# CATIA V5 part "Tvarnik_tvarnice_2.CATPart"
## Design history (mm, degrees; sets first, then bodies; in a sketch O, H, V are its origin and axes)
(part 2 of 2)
Body25 "Tvarnice"
  Sketch40 on face of Solid23, origin (1.6, 0, 0), H (0, 1, 0), V (0, 0, 1)
    line L1 (80, 80) -> (80, -80)
    line L2 (80, -80) -> (-80, -80)
    line L3 (-80, -80) -> (-80, 80)
    line L4 (-80, 80) -> (80, 80)
    length L4 = 160
    length L1 = 160
    vertical: L1 V, L3 V
    horizontal: L2 H, L4 H
    equidistance: L1 L3 O, L2 L4 O
  Pocket13: profile Sketch40, direction (-1, 0, 0), length 16
  Body26 "Vicko"
    Solid24: linked copy from another document
  Remove2: tool Body26
  Trim1: faces to keep start face of Pocket13, faces to remove start face of Pocket13 (x35)
  Sketch41 on start face of Pocket13, origin (1.6, 0, 0), H (0, 1, 0), V (0, 0, 1)
    projected circle E1 centre (26.45, -66.45) radius 5.1 from start face of Pocket13
    projected circle E2 centre (-26.2, -66.08) radius 5.1 from start face of Pocket13
    projected circle E3 centre (-68.2522, 13.0002) radius 5.1 from start face of Pocket13
    projected circle E4 centre (-35.5625, 59.6882) radius 5.1 from start face of Pocket13
    projected circle E5 centre (38.2049, 58.0324) radius 5.1 from start face of Pocket13
    projected circle E6 centre (70.2785, -7.2128) radius 5.1 from start face of Pocket13
  Pad6: profile Sketch41, direction (-1, 0, 0), length 3
  Sketch42 on end face of Pad6, origin (-1.4, 0, 0), H (0, 1, 0), V (0, 0, 1)
    projected circle E1 centre (70.2785, -7.2128) radius 3 from end face of Pad6
    projected circle E2 centre (38.2049, 58.0324) radius 3 from end face of Pad6
    projected circle E4 centre (-68.2522, 13.0002) radius 3 from edge [face of Solid24 | end face of Pad6]
    projected circle E5 centre (-26.2, -66.08) radius 3 from end face of Pad6
    projected circle E6 centre (26.45, -66.45) radius 3 from end face of Pad6
  Pad7: profile Sketch42, direction (-1, 0, 0), length 0.3
  Sketch43 on start face of Pocket13, origin (1.6, 0, 0), H (0, 1, 0), V (0, 0, 1)
    projected arc E1 centre (-39.7026, -63.67) radius 8 from (-33.5229, -68.7505) to (-31.75, -64.54) ccw from edge [face of Solid23 | face of Solid23]
    projected arc E3 centre (-38.7, -63.15) radius 7 from (-37.0577, -56.3454) to (-42.5892, -57.3299) ccw from edge [face of Solid23 | face of Solid23]
    projected arc E4 centre (-42.6448, -57.2467) radius 0.1 from (-42.6019, -57.337) to (-42.5892, -57.3299) ccw from edge [face of Solid23 | face of Solid23]
    projected line E5 (-42.9183, -57.4874) -> (-42.6019, -57.337) from edge [face of Solid23 | face of Solid23]
    projected arc E6 centre (-43.1328, -57.0357) radius 0.5 from (-43.5459, -57.3175) to (-42.9183, -57.4874) ccw from edge [face of Solid23 | face of Solid23]
    projected line E7 (-44.5334, -55.87) -> (-43.5459, -57.3175) from edge [face of Solid23 | face of Solid23]
    projected arc E8 centre (-44.9464, -56.1518) radius 0.5 from (-44.5334, -55.87) to (-44.634, -55.7614) ccw from edge [face of Solid23 | face of Solid23]
    projected arc E9 centre (0, 0) radius 71.425 from (-64.1739, -31.3568) to (-44.634, -55.7614) ccw from edge [face of Solid23 | face of Solid23]
    projected arc E10 centre (0, 0) radius 71.425 from (-71.1311, 6.4726) to (-64.1739, -31.3568) ccw from edge [face of Solid23 | face of Solid23]
    projected arc E11 centre (-73.1229, 6.6538) radius 2 from (-71.1311, 6.4726) to (-71.9052, 8.2404) ccw from edge [face of Solid23 | face of Solid23]
    projected arc E12 centre (-68.2522, 13.0002) radius 6 from (-69.8997, 18.7696) to (-71.9052, 8.2404) ccw from edge [face of Solid23 | face of Solid23]
    projected arc E13 centre (-70.4489, 20.6927) radius 2 from (-69.8997, 18.7696) to (-68.5299, 20.1291) ccw from edge [face of Solid23 | face of Solid23]
    projected arc E14 centre (0, 0) radius 71.425 from (-42.3563, 57.5107) to (-68.5299, 20.1291) ccw from edge [face of Solid23 | face of Solid23]
    projected arc E15 centre (-43.5423, 59.121) radius 2 from (-42.3563, 57.5107) to (-41.5474, 59.2628) ccw from edge [face of Solid23 | face of Solid23]
    projected arc E16 centre (-35.5625, 59.6882) radius 6 from (-32.3394, 64.749) to (-41.5474, 59.2628) ccw from edge [face of Solid23 | face of Solid23]
    projected arc E17 centre (-31.265, 66.4359) radius 2 from (-32.3394, 64.749) to (-30.8799, 64.4733) ccw from edge [face of Solid23 | face of Solid23]
    projected arc E18 centre (-31.265, 66.4359) radius 2 from (-30.8799, 64.4733) to (-30.4134, 64.6263) ccw from edge [face of Solid23 | face of Solid23]
    projected arc E19 centre (0, 0) radius 71.425 from (33.2826, 63.1965) to (-30.4134, 64.6263) ccw from edge [face of Solid23 | face of Solid23]
    projected arc E20 centre (34.2145, 64.9661) radius 2 from (33.2826, 63.1965) to (34.4133, 62.976) ccw from edge [face of Solid23 | face of Solid23]
    projected arc E21 centre (34.2145, 64.9661) radius 2 from (34.4133, 62.976) to (35.2121, 63.2327) ccw from edge [face of Solid23 | face of Solid23]
    projected arc E22 centre (38.2049, 58.0324) radius 6 from (44.1647, 57.3389) to (35.2121, 63.2327) ccw from edge [face of Solid23 | face of Solid23]
    projected arc E23 centre (46.1513, 57.1077) radius 2 from (44.1647, 57.3389) to (44.1679, 56.8506) ccw from edge [face of Solid23 | face of Solid23]
    projected arc E24 centre (46.1513, 57.1077) radius 2 from (44.1679, 56.8506) to (44.8942, 55.5522) ccw from edge [face of Solid23 | face of Solid23]
    projected arc E25 centre (0, 0) radius 71.425 from (68.6438, 19.7372) to (44.8942, 55.5522) ccw from edge [face of Solid23 | face of Solid23]
    projected arc E26 centre (68.5477, 19.7095) radius 0.1 from (68.6445, 19.7346) to (68.6438, 19.7372) ccw from edge [face of Solid23 | face of Solid23]
    projected arc E27 centre (68.5476, 19.7096) radius 0.1001 from (68.6357, 19.662) to (68.6445, 19.7346) ccw from edge [face of Solid23 | face of Solid23]
    projected arc E28 centre (68.5477, 19.7095) radius 0.1 from (68.6344, 19.6597) to (68.6357, 19.662) ccw from edge [face of Solid23 | face of Solid23]
    projected line E29 (65.7164, 14.5806) -> (68.6344, 19.6597) from edge [face of Solid23 | face of Solid23]
    projected arc E30 centre (69.5316, 12.3887) radius 4.4 from (65.7164, 14.5806) to (70.8571, 8.1931) ccw from edge [face of Solid23 | face of Solid23]
    projected arc E31 centre (70.8872, 8.0978) radius 0.1 from (70.9819, 8.13) to (70.8571, 8.1931) ccw from edge [face of Solid23 | face of Solid23]
    projected arc E33 centre (69.7785, -6.9628) radius 6 from (72.2645, -12.4235) to (75.4588, -5.0305) ccw from edge [face of Solid23 | face of Solid23]
    projected line E34 (70.9819, 8.13) -> (75.4588, -5.0305) from edge [face of Solid23 | face of Solid23]
    projected arc E35 centre (72.4717, -12.8786) radius 0.5 from (72.2645, -12.4235) to (72.1405, -12.504) ccw from edge [face of Solid23 | face of Solid23]
    projected line E36 (72.1405, -12.504) -> (72.0071, -12.6219) from edge [face of Solid23 | face of Solid23]
    projected line E37 (71.6567, -12.9317) -> (72.0071, -12.6219) from edge [face of Solid23 | face of Solid23]
    projected line E38 (70.1987, -14.2207) -> (71.6567, -12.9317) from edge [face of Solid23 | face of Solid23]
    projected arc E39 centre (70.861, -14.9699) radius 1 from (70.1987, -14.2207) to (69.8826, -14.7632) ccw from edge [face of Solid23 | face of Solid23]
    projected arc E40 centre (0, 0) radius 71.425 from (34.7, -62.4295) to (69.8826, -14.7632) ccw from edge [face of Solid23 | face of Solid23]
    projected line E41 (34.7, -63.3874) -> (34.7, -62.4295) from edge [face of Solid23 | face of Solid23]
    projected line E42 (34.7, -63.3874) -> (34.6998, -63.4087) from edge [face of Solid23 | face of Solid23]
    projected arc E43 centre (34.5768, -63.4037) radius 0.123 from (34.6907, -63.4503) to (34.6998, -63.4087) ccw from edge [face of Solid23 | face of Solid23]
    projected arc E45 centre (39.6, -65.7) radius 5.4 from (34.6823, -63.4692) to (34.2, -65.7) ccw from edge [face of Solid23 | face of Solid23]
    projected line E46 (34.6907, -63.4503) -> (34.6823, -63.4692) from edge [face of Solid23 | face of Solid23]
    projected arc E47 centre (27.2, -65.7) radius 7 from (29.0596, -72.4485) to (34.2, -65.7) ccw from edge [face of Solid23 | face of Solid23]
    projected line E48 (27.2179, -73.1928) -> (29.0487, -72.4522) from edge [face of Solid23 | face of Solid23]
    projected line E49 (27.2179, -73.1928) -> (27.1999, -73.1995) from edge [face of Solid23 | face of Solid23]
    projected line E50 (27.1999, -73.1995) -> (27.1807, -73.2) from edge [face of Solid23 | face of Solid23]
    projected line E51 (26.95, -73.2) -> (27.1807, -73.2) from edge [face of Solid23 | face of Solid23]
    projected arc E52 centre (26.95, -65.95) radius 7.25 from (19.7, -65.95) to (26.95, -73.2) ccw from edge [face of Solid23 | face of Solid23]
    projected line E53 (19.7, -54.5084) -> (19.7, -65.95) from edge [face of Solid23 | face of Solid23]
    projected arc E54 centre (10.55, -54.5084) radius 9.15 from (19.7, -54.5084) to (14.5407, -46.2746) ccw from edge [face of Solid23 | face of Solid23]
    projected arc E55 centre (10.55, -54.5084) radius 9.15 from (14.5407, -46.2746) to (12.2, -45.5084) ccw from edge [face of Solid23 | face of Solid23]
    projected arc E56 centre (-1.5593, -117.2) radius 73 from (12.028, -45.4756) to (8.5876, -44.9086) ccw from edge [face of Solid23 | face of Solid23]
    projected arc E57 centre (-1.5593, -117.2) radius 73 from (12.2, -45.5084) to (12.028, -45.4756) ccw from edge [face of Solid23 | face of Solid23]
    projected arc E58 centre (-1.5593, -117.2) radius 73 from (8.5876, -44.9086) to (-13.7, -45.2166) ccw from edge [face of Solid23 | face of Solid23]
    projected arc E59 centre (-12.6167, -52.2166) radius 7.0833 from (-13.7, -45.2166) to (-14.8563, -45.4967) ccw from edge [face of Solid23 | face of Solid23]
    projected arc E60 centre (-12.6167, -52.2166) radius 7.0833 from (-14.8563, -45.4967) to (-19.7, -52.2166) ccw from edge [face of Solid23 | face of Solid23]
    projected line E61 (-19.7, -52.2166) -> (-19.7, -67.2) from edge [face of Solid23 | face of Solid23]
    projected arc E62 centre (-25.7, -67.2) radius 6 from (-25.7, -73.2) to (-19.7, -67.2) ccw from edge [face of Solid23 | face of Solid23]
    projected line E63 (-25.7, -73.2) -> (-25.725, -73.1988) from edge [face of Solid23 | face of Solid23]
    projected line E64 (-25.7279, -73.1975) -> (-25.7474, -73.1876) from edge [face of Solid23 | face of Solid23]
    point P123 (-25.7279, -73.1975)
    projected line E65 (-25.7474, -73.1876) -> (-28.2581, -71.7985) from edge [face of Solid23 | face of Solid23]
    projected line E66 (-33.494, -68.9015) -> (-28.2581, -71.7985) from edge [face of Solid23 | face of Solid23]
    projected arc E67 centre (-33.4456, -68.814) radius 0.1 from (-33.5229, -68.7505) to (-33.494, -68.9015) ccw from edge [face of Solid23 | face of Solid23]
    line L1 (29.0487, -72.4522) -> (29.0596, -72.4485)
    line L2 (-25.7279, -73.1975) -> (-25.725, -73.1988)
    point P131 (-25.7279, -73.1975)
    coincidence: P131 E64, P123 P131
  Pad8: profile Sketch43, direction (-1, 0, 0), length 0.3
  Sketch44 on end face of Pocket13, origin (-14.4, 0, 0), H (0, -1, 0), V (0, 0, 1)
    line L1 (90, 90) -> (90, -90)
    line L2 (90, -90) -> (-90, -90)
    line L3 (-90, -90) -> (-90, 90)
    line L4 (-90, 90) -> (90, 90)
    length L4 = 180
    length L1 = 180
    vertical: L1 V, L3 V
    horizontal: L2 H, L4 H
    equidistance: L1 L3 O, L2 L4 O
  Pocket14: profile Sketch44, direction (-1, 0, 0), length 30
  DatumCurve25
  DatumCurve26
  Body27 "MANIFOLD_SOLID_BREP #135"
  Remove3: tool Body27
  DatumSurface19
  Sketch45 on zx-plane, origin (0, 0, 0), H (-1, 0, 0), V (0, 0, 1)
    point P1 (5.1, 0)
    line L1 (5.1, 0) -> (5.1, 1)
    arc A1 centre (8.8103, -0.4945) radius 4 from (5.1, 1) to (8.6, 3.5) cw
    line L2 (8.6, 3.5) -> (8.6, 0)
    point P5 (8.6, 0)
    line L3 (8.6, 0) -> (5.1, 0)
    length L1 = 1
    radius A1 = 4
    length L2 = 3.5
    length L3 = 3.5
    distance L1 V = 5.1
    coincidence: P1 H, P5 H
    vertical: L1 V, L2 V
    horizontal: L3 H
  Shaft1: profile Sketch45, axis Sketch45.L3, angle 360
  Sketch46 on end face of Pocket14, origin (-44.4, 0, 0), H (0, -1, 0), V (0, 0, 1)
    arc A1 centre (0, 0) radius 18.5 from (-18.5, 0) to (18.5, 0) ccw
    arc A2 centre (0, 0) radius 18.5 from (18.5, 0) to (-18.5, 0) ccw
  Pad9: profile Sketch46, direction (1, 0, 0), length 29
  DatumCurve27
  DatumCurve28
  Sketch47 on end face of Pad9, origin (-15.4, 0, 0), H (0, -1, 0), V (0, 0, 1)
    projected arc E1 centre (0, 0) radius 8.5 from (8.5, 0) to (-8.5, 0) ccw from edge of DatumCurve27
    projected arc E2 centre (0, 0) radius 8.5 from (-8.5, 0) to (8.5, 0) ccw from edge of DatumCurve28
  Pad10: profile Sketch47, direction (1, 0, 0), length 6.8
  Sketch48 on face of Pocket14 from Sketch44.L4, origin (0, 0, 90), H (1, 0, 0), V (0, 1, 0)
    circle A1 centre (-30.4, -33) radius 5
    circle A2 centre (-30.4, 33) radius 5
    circle A3 centre (-30.4, 65) radius 5
    circle A4 centre (-30.4, -65) radius 5
    radius A3 = 5
    radius A2 = 5
    radius A4 = 5
    radius A1 = 5
  Pad11: profile Sketch48, direction (0, 0, -1), up to the existing solid (limit type 2), offset 30
  Sketch49 on face of Solid24, origin (0, -11.5, 0), H (1, 0, 0), V (0, 0, 1)
    projected line E1 (-0.4, -44.8326) -> (-0.4, -42) from edge [face of Solid24 | face of Solid24]
    projected line E2 (-0.8, -42) -> (-0.8, -43.8052) from edge [face of Solid24 | face of Solid24]
    projected line E3 (-0.8, -42) -> (-0.4, -42) from edge [face of Solid24 | face of Solid24]
    projected arc E4 centre (-0.9006, -43.8056) radius 0.1006 from (-0.8933, -43.906) to (-0.8, -43.8052) ccw from edge [face of Solid24 | face of Solid24]
    projected line E5 (-2.8, -44.0344) -> (-0.8933, -43.906) from edge [face of Solid24 | face of Solid24]
    projected line E6 (-0.4, -44.8326) -> (-2.8, -44.7051) from edge [face of Solid24 | face of Solid24]
    line L1 (-2.8, -44.0344) -> (-2.9283, -44.043)
    line L2 (-2.8, -44.7051) -> (-2.9283, -44.6983)
    line L3 (-2.9283, -44.043) -> (-2.9283, -44.6983)
    distance L3 E1 = 2.5283
    tangency: L1 E4
    parallelism: L2 E6
    vertical: L3 V
  Sketch50 on start face of Pocket13, origin (1.6, 0, 0), H (0, 1, 0), V (0, 0, 1)
    projected arc E1 centre (-1.5593, -117.2) radius 73 from (4.4821, -44.4504) to (-13.7, -45.2166) ccw from edge [face of Solid24 | face of Pad8]
    projected arc E2 centre (-1.5593, -117.2) radius 73 from (11.5, -45.3776) to (-11.5, -44.88) ccw from edge [face of Solid24 | face of Pad8]
  Rib1: profile Sketch49, centre curve Sketch50
  Sketch51 on face of Solid24, origin (0, -6.5, 0), H (-1, 0, 0), V (0, 0, 1)
    projected line E1 (2.8, -43.4939) -> (0.8933, -43.3665) from edge [face of Solid24 | face of Solid24]
    projected arc E2 centre (0.9002, -43.2665) radius 0.1002 from (0.8, -43.2664) to (0.8933, -43.3665) ccw from edge [face of Solid24 | face of Solid24]
    line L1 (2.8, -43.4939) -> (2.9232, -43.5022)
    line L2 (2.9232, -43.5022) -> (2.9232, -43.6038)
    line L3 (2.9232, -43.6038) -> (0.8, -43.4619)
    line L4 (0.8, -43.4619) -> (0.8, -43.2664)
    length L4 = 0.1955
    distance L2 L4 = 2.1232
    tangency: L1 E2
    vertical: L2 V, L4 V
    parallelism: L3 E1
  Sketch52 on face of Rib1, origin (-0.8, 0, 0), H (0, 1, 0), V (0, 0, 1)
    arc A1 centre (11.724, -229.4952) radius 187.1183 from (-6.5, -43.2664) to (-11.5, -43.8237) ccw
    point P2 (-6.5, -43.2664)
    point P3 (-11.5, -43.8237)
    reference projected line E1 (-11.5, -43.906) -> (-11.5, -43.8052) from edge [face of Rib1 | face of Solid24]
    reference projected line E2 (-6.5, -43.3667) -> (-6.5, -43.2664) from Sketch51.E2
    reference projected point E3 (-6.5, -43.2664) from vertex [element of Sketch51 | element of Sketch51]
    radius A1 = 187.1183
    distance P3 E1 = 0
    distance P2 E2 = 0
    distance P2 E3 = 0
  Rib2: profile Sketch51, centre curve Sketch52
  Body28
    Solid25: solid without history
  Remove4: tool Body28
  Body29 "MANIFOLD_SOLID_BREP #135"
    Solid26: solid without history
  Remove5: tool Body29
  Body30 "MANIFOLD_SOLID_BREP #135"
    Solid27: solid without history
  Remove6: tool Body30
  DatumCurve29 to DatumCurve31
  Sketch53 on start face of Pocket13, origin (1.6, 0, 0), H (0, 1, 0), V (0, 0, 1)
    projected line E1 (16.5, -79.5001) -> (16.5, -50.5001) from edge of DatumCurve29
    projected line E2 (-15, -50.0001) -> (16, -50.0001) from edge of DatumCurve30
    projected line E3 (-15.5, -50.5001) -> (-15.5, -79.5001) from edge of DatumCurve31
    line L1 (-15.5, -50.5001) -> (-15.5, -50.0001)
    point P7 (-15.5, -50.0001)
    line L2 (-15.5, -50.0001) -> (-15, -50.0001)
    line L3 (16, -50.0001) -> (16.5, -50.0001)
    point P8 (16.5, -50.0001)
    line L4 (16.5, -50.5001) -> (16.5, -50.0001)
    line L5 (16.5, -79.5001) -> (16.5, -80)
    reference projected line E4 (-80, -80) -> (80, -80) from edge [face of Pocket13 from Sketch40.L2 | start face of Pocket13]
    line L6 (-15.5, -79.5001) -> (-15.5, -80)
    point P10 (-15.5, -80)
    line L7 (-15.5, -80) -> (16.5, -80)
    distance P10 E4 = 0
    coincidence: P7 E2, P8 E1
    vertical: L1 V, L4 V, L5 V, L6 V
    horizontal: L2 H, L3 H, L7 H
  Pad12: profile Sketch53, direction (-1, 0, 0), length 1
  Fillet10: radius 0.5, on edge [face of Pad12 from Sketch53.L1 | face of Pad12 from Sketch53.L2]; edge [face of Pad12 from Sketch53.L3 | face of Pad12 from Sketch53.L4]
  Sketch54 on face of Solid24, origin (-0.4, 0, 0), H (0, 1, 0), V (0, 0, 1)
  Pad13: profile Sketch54, direction (1, 0, 0), up to face of Rib1
  Sketch55 on face of Solid27, origin (-2.9, 0, 0), H (0, 1, 0), V (0, 0, 1)
    point P2 (11.556, -45.2065)
    point P3 (11.5, -45.1961)
    point P4 (11.556, -45.2065)
    point P5 (11.5, -45.1961)
    point P7 (11.5756, -45.1469)
    line L1 (-10.5, -44.5697) -> (-10.5005, -44.5655)
    point P9 (-10.5005, -44.5655)
    line L2 (11.575, -45.1486) -> (11.556, -45.2065)
    line L3 (11.5, -45.1961) -> (11.556, -45.2065)
    arc A1 centre (-1.5593, -117.2) radius 73.1786 from (11.5, -45.1961) to (-10.5, -44.5697) ccw
    construction arc A2 centre (-1.3665, -117.1471) radius 73.1541 from (11.5756, -45.1469) to (-11.5, -44.6983) ccw
    arc A3 centre (-1.3665, -117.1471) radius 73.1541 from (11.5756, -45.1469) to (-10.5005, -44.5655) ccw
    line L4 (11.5756, -45.1469) -> (11.575, -45.1486)
    point P10 (11.5756, -45.1469)
    distance P9 A2 = 0
    coincidence: P10 L2, P2 P4, P3 P5, P7 P10
    parallelism: L4 L2
  Pocket15: profile Sketch55, direction (-1, 0, 0), through (limit type 6)
  Sketch56 on face of Solid24, origin (0, 11.5, 0), H (-1, 0, 0), V (0, 0, 1)
    projected line E1 (2.8, -44.4098) -> (2.4333, -44.385) from edge [face of Solid24 | face of Solid24]
    projected line E2 (2.4333, -44.385) -> (0.9333, -44.2835) from edge [face of Solid24 | face of Solid27]
    projected arc E3 centre (0.9009, -44.1801) radius 0.1009 from (0.8, -44.1794) to (0.8933, -44.2807) ccw from edge [face of Solid24 | face of Solid24]
    projected line E4 (0.8, -44.1794) -> (0.8, -44.2927) from edge [face of Rib1 | face of Solid24]
    line L1 (2.8, -44.4098) -> (2.9352, -44.419)
    line L2 (2.9352, -44.419) -> (2.9352, -44.5527)
    line L3 (0.9333, -44.2835) -> (0.8933, -44.2807)
    line L4 (0.8, -44.2927) -> (0.8, -44.4874)
    point P11 (0.8, -44.4874)
    line L5 (0.8, -44.4874) -> (2.9352, -44.5527)
    point P12 (0.8, -44.4874)
    length L2 = 0.1337
    distance L2 E4 = 2.1352
    length L4 = 0.1946
    angle L4 E4 = 180
    distance P12 P11 = 0
    parallelism: L1 E1
    vertical: L2 V
    tangency: L3 E3
    coincidence: P12 L4
  Sketch57 on face of Rib1, origin (-0.8, 0, 0), H (0, 1, 0), V (0, 0, 1)
    arc A1 centre (0.636, -103.301) radius 60 from (11.5, -44.2927) to (6.5, -43.5882) ccw
    point P2 (11.5, -44.2927)
    point P3 (6.5, -43.5882)
    reference projected point E1 (11.5, -44.2927) from vertex [element of Sketch56 | element of Sketch56]
    reference projected line E2 (11.5, -44.1794) -> (11.5, -44.2927) from Sketch56.E4
    reference projected point E3 (6.5, -43.5882) from vertex [face of Solid27 | face of Solid24 | face of Rib1]
    arc A2 centre (-3.3808, -144.2033) radius 101.099 from (6.5, -43.5882) to (2.5, -43.2754) ccw
    point P5 (2.5, -43.2754)
    reference projected line E4 (2.5, -42) -> (2.5, -43.1646) from edge [face of Rib1 | face of Solid24]
    reference projected line E5 (2.4736, -43.2741) -> (2.4999, -43.2754) from edge [face of Solid27 | face of Rib1]
    arc A3 centre (-0.9804, -102.9994) radius 59.8253 from (2.5, -43.2754) to (-2.6, -43.196) ccw
    point P7 (-2.6, -43.196)
    reference projected line E6 (-2.5, -42) -> (-2.5, -43.0842) from edge [face of Solid24 | face of Rib1]
    reference projected point E7 (-2.5, -43.141) from vertex [face of Solid24 | face of Rib1 | face of Rib1]
    radius A1 = 60
    distance P2 E1 = 0
    distance P2 E2 = 0
    distance P3 E3 = 0
    distance P5 E4 = 0
    distance P5 E5 = 0
    distance P7 E6 = 0.1
    distance P7 E7 V = 0.055
    tangency: A2 A1, A3 A2
  Rib3: profile Sketch56, centre curve Sketch57
  DatumCurve32
  DatumCurve33
  Sketch58 on start face of Pocket13, origin (1.6, 0, 0), H (0, 1, 0), V (0, 0, 1)
    projected line E1 (-11, -44.2759) -> (-11, -49.5001) from edge of DatumCurve32
    projected line E2 (-11, -44.813) -> (-11, -49.5001) from edge of DatumCurve32
    projected line E3 (12, -44.7902) -> (12, -49.5001) from edge of DatumCurve33
    projected line E4 (12, -45.4703) -> (12, -49.5001) from edge of DatumCurve33
    projected arc E5 centre (-1.5593, -117.2) radius 73 from (8.5876, -44.9086) to (-13.7, -45.2166) ccw from edge [start face of Pocket13 | face of Pad8]
    projected arc E6 centre (-1.5593, -117.2) radius 73 from (12.028, -45.4756) to (8.5876, -44.9086) ccw from edge [start face of Pocket13 | face of Pad8]
    point P9 (12, -45.4703)
    point P10 (-11, -44.813)
    line L1 (12, -49.5001) -> (12, -50.2244)
    line L2 (12, -50.2244) -> (-11, -50.2244)
    point P12 (-11, -50.2244)
    line L3 (-11, -49.5001) -> (-11, -50.2244)
    offset arc E7 centre (-1.5593, -117.2) radius 73.2871 from (8.6275, -44.6243) to (-13.7478, -44.9335) ccw from edge [start face of Pocket13 | face of Pad8]
    offset arc E8 centre (-1.5593, -117.2) radius 73.2871 from (8.6275, -44.6243) to (-11, -44.5235) ccw from edge [start face of Pocket13 | face of Pad8]
    offset arc E9 centre (-1.5593, -117.2) radius 73.2871 from (12.0814, -45.1935) to (8.6275, -44.6243) ccw from edge [start face of Pocket13 | face of Pad8]
    offset arc E10 centre (-1.5593, -117.2) radius 73.2871 from (12, -45.1781) to (8.6275, -44.6243) ccw from edge [start face of Pocket13 | face of Pad8]
    point P17 (8.5876, -44.6187)
    line L4 (12, -45.4703) -> (12, -45.1781)
    point P18 (12, -45.4703)
    point P19 (12, -45.1781)
    line L5 (-11, -44.813) -> (-11, -44.5235)
    point P20 (-11, -44.5235)
    distance L2 P10 = 5.4114
    length L4 = 0.2922
    coincidence: E6 P9, E5 P10, P12 E1, E9 P17, P17 E7, P18 E6, P19 E9, P20 E7
    vertical: L1 V, L3 V, L4 V, L5 V
    horizontal: L2 H
  Pad14: profile Sketch58, direction (-1, 0, 0), length 2.5
  Chamfer2: length 5, angle 45, on edge [face of Pocket14 from Sketch44.L1 | face of Pocket14 from Sketch44.L2]; edge [face of Pocket13 from Sketch40.L4 | face of Pocket13 from Sketch40.L3]; edge [face of Pocket14 from Sketch44.L4 | face of Pocket14 from Sketch44.L1]; edge [face of Pocket13 from Sketch40.L3 | face of Pocket13 from Sketch40.L2]; edge [face of Pocket13 from Sketch40.L1 | face of Pocket13 from Sketch40.L4]; edge [face of Pocket14 from Sketch44.L3 | face of Pocket14 from Sketch44.L4]; edge [face of Pocket13 from Sketch40.L2 | face of Pocket13 from Sketch40.L1]; edge [face of Pocket14 from Sketch44.L2 | face of Pocket14 from Sketch44.L3]
  Sketch59 on face of Pocket14 from Sketch44.L4, origin (0, 0, 90), H (1, 0, 0), V (0, 1, 0)
    circle A1 centre (-30.4, 65) radius 6
    circle A2 centre (-30.4, 33) radius 6
    circle A3 centre (-30.4, -33) radius 6
    circle A4 centre (-30.4, -65) radius 6
    reference projected line E3 (-44.4, -90) -> (-44.4, 90) from edge [face of Pocket14 from Sketch44.L4 | end face of Pocket14]
    reference intersected line E4 (-14.4, -85) -> (-44.4, -85) from face of Chamfer2
    reference projected line E5 (-14.4, 85) -> (-44.4, 85) from edge [face of Chamfer2 | face of Pocket14 from Sketch44.L4]
    reference projected line E6 (-14.4, 90) -> (-44.4, 90) from edge [face of Pocket14 from Sketch44.L3 | face of Chamfer2]
    radius A4 = 6
    radius A3 = 6
    radius A2 = 6
    radius A1 = 6
    distance A1 E3 = 20
    distance A2 E3 = 8
    distance A3 E3 = 20
    distance A4 E3 = 8
    distance A4 E4 = 26
    distance A4 A3 = 32
    distance A2 E5 = 58
    distance A1 E6 = 19
  Pad15: profile Sketch59, direction (0, 0, -1), length 1
  Mirror1: of Pad15, about xy-plane
  Sketch60 on face of Pad14, origin (0, 12, 0), H (1, 0, 0), V (0, 0, 1)
    projected line E1 (1.6, -45.4703) -> (1.3, -45.4703) from edge [face of Pad8 | face of Pad14]
    projected line E2 (1.3, -45.4703) -> (1.3, -45.4509) from edge [end face of Pad8 | face of Pad14]
    projected line E3 (1.3, -45.4703) -> (1.3, -45.4513) from edge [end face of Pad8 | face of Pad14]
    line L1 (1.3, -45.4513) -> (1.6, -45.4513)
    line L2 (1.6, -45.4513) -> (1.6, -45.4703)
    point P6 (1.3, -45.4513)
    point P7 (1.3, -45.4513)
    distance L1 E1 = 0.019
    vertical: L2 V
    coincidence: L1 P6, E2 P7
  Sketch61 on start face of Pocket13, origin (1.6, 0, 0), H (0, 1, 0), V (0, 0, 1)
    projected arc E1 centre (10.55, -54.5084) radius 9.15 from (14.5407, -46.2746) to (12.2, -45.5084) ccw from edge [start face of Pocket13 | face of Pad8]
    projected arc E2 centre (10.55, -54.5084) radius 9.15 from (19.7, -54.5084) to (14.5407, -46.2746) ccw from edge [start face of Pocket13 | face of Pad8]
    projected line E3 (19.7, -54.5084) -> (19.7, -65.95) from edge [start face of Pocket13 | face of Pad8]
    projected arc E4 centre (26.95, -65.95) radius 7.25 from (19.7, -65.95) to (26.95, -73.2) ccw from edge [start face of Pocket13 | face of Pad8]
    projected line E5 (26.95, -73.2) -> (27.1807, -73.2) from edge [start face of Pocket13 | face of Pad8]
    projected line E6 (27.2179, -73.1928) -> (29.0487, -72.4522) from edge [start face of Pocket13 | face of Pad8]
    projected arc E7 centre (27.2, -65.7) radius 7 from (29.0596, -72.4485) to (34.2, -65.7) ccw from edge [start face of Pocket13 | face of Pad8]
    projected line E8 (34.7, -63.3874) -> (34.7, -62.4295) from edge [start face of Pocket13 | face of Pad8]
    projected arc E9 centre (34.5768, -63.4037) radius 0.123 from (34.6907, -63.4503) to (34.6998, -63.4087) ccw from edge [start face of Pocket13 | face of Pad8]
    projected line E10 (34.6823, -63.4692) -> (34.6907, -63.4503) from edge [start face of Pocket13 | face of Pad8]
    projected line E11 (34.6998, -63.4087) -> (34.7, -63.3874) from edge [start face of Pocket13 | face of Pad8]
    projected arc E12 centre (-1.5593, -117.2) radius 73 from (12.2, -45.5084) to (12.028, -45.4756) ccw from edge [start face of Pocket13 | face of Pad8]
    projected arc E13 centre (-1.5593, -117.2) radius 73 from (12.028, -45.4756) to (12, -45.4703) ccw from edge [start face of Pocket13 | face of Pad8]
    projected line E14 (29.0487, -72.4522) -> (29.0596, -72.4485) from edge [start face of Pocket13 | face of Pad8 from Sketch43.L1]
    projected line E15 (27.1999, -73.1995) -> (27.2179, -73.1928) from edge [start face of Pocket13 | face of Pad8]
    projected line E16 (27.1807, -73.2) -> (27.1999, -73.1995) from edge [start face of Pocket13 | face of Pad8]
    line L1 (34.2, -65.7) -> (34.6823, -63.4692)
  Fillet11: radius 0.5, on edge [face of Pad14 from Sketch58.L1 | face of Pad12]
  Fillet12: radius 0.5, on edge [face of Pad12 | face of Pad14 from Sketch58.L3]
  DatumSurface20
  Sketch62 on face of Rib1, origin (-0.8, 0, 0), H (0, 1, 0), V (0, 0, 1)
    projected arc E1 centre (-1.1745, -116.1657) radius 73.0936 from (-2.6232, -43.0865) to (-6.5, -43.2664) ccw from edge [face of Solid24 | face of Rib1]
    point P4 (-7.8538, -43.403)
    projected arc E3 centre (-1.5593, -117.2) radius 74.065 from (-7.8538, -43.403) to (-11.5, -43.8052) ccw from edge [face of Rib1 | face of Rib1]
    projected arc E4 centre (-1.5593, -117.2) radius 74.065 from (-7.8538, -43.403) to (-11, -43.7392) ccw from edge [face of Rib1 | face of Rib1]
    point P5 (-7.8538, -43.403)
    projected arc E7 centre (0.636, -103.301) radius 60.1101 from (11.5, -44.1808) to (6.5, -43.4776) ccw from edge [face of Rib1 | face of Rib3]
    line L1 (-11, -43.7392) -> (-11, -42)
    line L2 (12, -44.2693) -> (12, -41.9648)
    projected line E9 (2.5, -42) -> (-2.5, -42) from edge [face of Solid23 | face of Solid23]
    projected line E10 (-6.5, -42) -> (-11.5, -42) from edge [face of Solid23 | face of Solid23]
    projected line E11 (-6.5, -42) -> (-11, -42) from edge [face of Solid23 | face of Solid23]
    line L3 (-6.5, -42) -> (-2.5, -42)
    line L4 (2.5, -42) -> (6.5, -42)
    line L5 (11.5, -42) -> (12, -41.9648)
    point P22 (-11, -42)
    point P23 (-11, -43.7392)
    point P24 (-11, -43.7392)
    point P25 (-11, -42)
    line L6 (11.5, -42) -> (6.5, -42)
    line L7 (11.5, -44.1808) -> (12, -44.2693)
    length L5 = 0.5012
    length L2 = 2.3044
    length L1 = 1.7392
    length L7 = 0.5078
    vertical: L1 V, L2 V
    horizontal: L3 H, L4 H, L6 H
    tangency: L5 E1
    coincidence: L1 P22, L1 P23, E3 P24, E10 P25, P4 P5, P22 P25, P23 P24
  Pocket16: profile Sketch62, direction (-1, 0, 0), up to face of DatumSurface20
  Sketch63 on end face of Pocket16, origin (-0.4, 0, 0), H (0, 1, 0), V (0, 0, 1)
    projected arc E1 centre (-1.5593, -117.2) radius 74.065 from (-7.8538, -43.403) to (-11, -43.7392) ccw from edge [end face of Pocket16 | face of Pocket16 from Sketch62.E4]
    projected arc E3 centre (-1.1745, -116.1657) radius 73.0936 from (-2.6232, -43.0865) to (-6.5, -43.2664) ccw from edge [end face of Pocket16 | face of Pocket16 from Sketch62.E1]
    projected arc E6 centre (0.636, -103.301) radius 60.1101 from (11.5, -44.1808) to (6.5, -43.4776) ccw from edge [end face of Pocket16 | face of Pocket16 from Sketch62.E7]
    projected line E7 (11.5, -44.1808) -> (12, -44.2693) from edge [face of Pocket16 from Sketch62.L7 | end face of Pocket16]
    line L1 (12, -44.2693) -> (12, -44.3707)
    projected arc E8 centre (-1.1745, -116.1657) radius 72.9938 from (12.8406, -44.53) to (11.5, -44.2807) ccw from edge [face of Solid24 | face of Solid24]
    projected arc E9 centre (-1.1745, -116.1657) radius 72.9938 from (12, -44.3707) to (11.5, -44.2807) ccw from edge [face of Solid24 | face of Solid24]
    projected arc E10 centre (0.6353, -103.306) radius 60.0169 from (11.5, -44.2807) to (6.499, -43.5763) ccw from edge [face of Rib3 | face of Rib3]
    projected arc E11 centre (0.6353, -103.306) radius 60.0169 from (11.5, -44.2807) to (6.5067, -43.577) ccw from edge [face of Rib3 | face of Rib3]
    projected arc E13 centre (-0.9806, -103.0128) radius 59.8505 from (2.4992, -43.2635) to (-2.6027, -43.1843) ccw from edge [face of Rib3 | face of Rib3]
    projected arc E14 centre (-0.9806, -103.0128) radius 59.8505 from (2.4992, -43.2635) to (-2.5861, -43.1838) ccw from edge [face of Rib3 | face of Rib3]
    projected arc E15 centre (-1.1745, -116.1657) radius 72.9938 from (-2.6021, -43.1859) to (-6.5, -43.3665) ccw from edge [face of Solid24 | face of Solid24]
    projected arc E16 centre (-0.0968, -126.2946) radius 83.1736 from (-6.5688, -43.3732) to (-7.8119, -43.4796) ccw from edge [face of Rib2 | face of Solid27]
    projected line E17 (-6.5, -43.3665) -> (-6.5688, -43.3732) from edge [face of Rib2 | face of Rib2]
    projected arc E18 centre (-1.2115, -116.5013) radius 73.3194 from (-7.8119, -43.4796) to (-10.5642, -43.7809) ccw from edge [face of Solid27 | face of Rib1]
    projected arc E19 centre (-1.5593, -117.2001) radius 73.9652 from (-10.6303, -43.7932) to (-11.5, -43.906) ccw from edge [face of Rib1 | face of Rib1]
    projected arc E20 centre (-1.5593, -117.2001) radius 73.9652 from (-10.6303, -43.7932) to (-11, -43.8399) ccw from edge [face of Rib1 | face of Rib1]
    projected line E21 (-10.6303, -43.7932) -> (-10.5642, -43.7809) from edge [face of Solid27 | face of Rib1]
    line L2 (-11, -43.7392) -> (-11, -43.8399)
    point P36 (-11, -43.7392)
    point P37 (-11, -43.8399)
    point P38 (12, -44.3707)
    point P39 (12, -44.3707)
    reference projected point E22 (-1.1745, -116.1657) from edge
    line L3 (6.5, -43.5765) -> (6.5067, -43.577)
    point P40 (6.5067, -43.577)
    line L4 (-2.6021, -43.1859) -> (-2.5861, -43.1838)
    distance L1 E22 = 13.1745
    length L2 = 0.1007
    vertical: L1 V, L2 V
    coincidence: P36 E1, P37 E19, L1 P38, E8 P39, P40 E10, P38 P39
  Pocket17: profile Sketch63, direction (-1, 0, 0), through (limit type 6)
  Sketch64 on face of Solid24, origin (-0.8, 0, 0), H (0, 1, 0), V (0, 0, 1)
    projected circle E2 centre (0, 0) radius 1 from face of Solid24
    projected line E4 (4.3785, -1.9253) -> (4.3785, 3.3747) from edge [face of Solid24 | face of Solid24]
    projected arc E5 centre (2.3785, 3.3747) radius 2 from (4.3785, 3.3747) to (2.3785, 5.3747) ccw from edge [face of Solid24 | face of Solid24]
    projected line E6 (2.3785, 5.3747) -> (-22.6215, 5.3747) from edge [face of Solid24 | face of Solid24]
    projected arc E7 centre (-22.6215, 3.3747) radius 2 from (-22.6215, 5.3747) to (-24.6215, 3.3747) ccw from edge [face of Solid24 | face of Solid24]
    projected line E8 (-24.6215, 3.3747) -> (-24.6215, -1.9253) from edge [face of Solid24 | face of Solid24]
    projected line E9 (-24.6215, -1.9253) -> (-30.5215, -1.9253) from edge [face of Solid24 | face of Solid24]
    projected arc E10 centre (-30.5215, -3.9253) radius 2 from (-30.5215, -1.9253) to (-32.5215, -3.9253) ccw from edge [face of Solid24 | face of Solid24]
    projected line E11 (-32.5215, -3.9253) -> (-32.5215, -19.9253) from edge [face of Solid24 | face of Solid24]
    projected arc E12 centre (-30.5215, -19.9253) radius 2 from (-32.5215, -19.9253) to (-30.5215, -21.9253) ccw from edge [face of Solid24 | face of Solid24]
    projected line E13 (-30.5215, -21.9253) -> (10.2785, -21.9253) from edge [face of Solid24 | face of Solid24]
    projected arc E14 centre (10.2785, -19.9253) radius 2 from (10.2785, -21.9253) to (12.2785, -19.9253) ccw from edge [face of Solid24 | face of Solid24]
    projected line E15 (12.2785, -19.9253) -> (12.2785, -3.9253) from edge [face of Solid24 | face of Solid24]
    projected arc E16 centre (10.2785, -3.9253) radius 2 from (12.2785, -3.9253) to (10.2785, -1.9253) ccw from edge [face of Solid24 | face of Solid24]
    projected line E17 (10.2785, -1.9253) -> (4.3785, -1.9253) from edge [face of Solid24 | face of Solid24]
    projected arc E18 centre (2.3785, 10.8747) radius 2 from (2.3785, 8.8747) to (4.3785, 10.8747) ccw from edge [face of Solid24 | face of Solid24]
    projected line E19 (-22.6215, 8.8747) -> (2.3785, 8.8747) from edge [face of Solid24 | face of Solid24]
    projected arc E20 centre (-22.6215, 10.8747) radius 2 from (-24.6215, 10.8747) to (-22.6215, 8.8747) ccw from edge [face of Solid24 | face of Solid24]
    projected line E21 (-24.6215, 16.1747) -> (-24.6215, 10.8747) from edge [face of Solid24 | face of Solid24]
    projected line E22 (-30.5215, 16.1747) -> (-24.6215, 16.1747) from edge [face of Solid24 | face of Solid24]
    projected arc E23 centre (-30.5215, 18.1747) radius 2 from (-32.5215, 18.1747) to (-30.5215, 16.1747) ccw from edge [face of Solid24 | face of Solid24]
    projected line E24 (-32.5215, 34.1747) -> (-32.5215, 18.1747) from edge [face of Solid24 | face of Solid24]
    projected arc E25 centre (-30.5215, 34.1747) radius 2 from (-30.5215, 36.1747) to (-32.5215, 34.1747) ccw from edge [face of Solid24 | face of Solid24]
    projected line E26 (10.2785, 36.1747) -> (-30.5215, 36.1747) from edge [face of Solid24 | face of Solid24]
    projected arc E27 centre (10.2785, 34.1747) radius 2 from (12.2785, 34.1747) to (10.2785, 36.1747) ccw from edge [face of Solid24 | face of Solid24]
    projected line E28 (12.2785, 18.1747) -> (12.2785, 34.1747) from edge [face of Solid24 | face of Solid24]
    projected arc E29 centre (10.2785, 18.1747) radius 2 from (10.2785, 16.1747) to (12.2785, 18.1747) ccw from edge [face of Solid24 | face of Solid24]
    projected line E30 (4.3785, 16.1747) -> (10.2785, 16.1747) from edge [face of Solid24 | face of Solid24]
    projected line E31 (4.3785, 10.8747) -> (4.3785, 16.1747) from edge [face of Solid24 | face of Solid24]
  Pocket18: profile Sketch64, direction (-1, 0, 0), up to face of Solid24
  Chamfer3: length 4.3, second length 0.5, on edge [face of Solid24 | face of Pocket18] (x16)
  Fillet13: radius 1, on edge [face of Chamfer3 | face of Chamfer3] (x15)
  Fillet14: radius 1, on edge [face of Chamfer3 | face of Chamfer3]
  Fillet15: radius 1, on edge [face of Solid24 | face of Chamfer3] (x2); face of Solid24; edge [face of Chamfer3 | face of Solid24]
  Fillet16: radius 0.5, on edge [face of Solid24 | face of Solid24]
